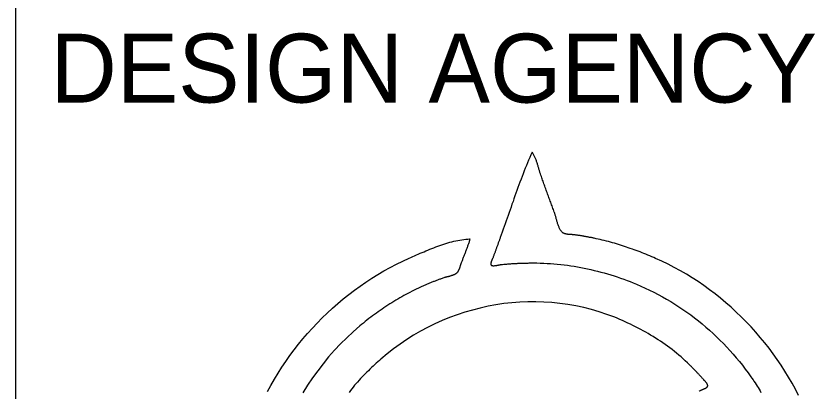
# Model space of a CAD drawing. Extents: x 0 to 34, y 0 to 22.
# Drawn here: x 32 to 33.162, y 4.431 to 4.976 of the extents above; entities that cross this region are included whole.
import ezdxf

# ---------------------------------------------------------------- set-up
doc = ezdxf.new("R2010")
doc.units = 0
for name, color, linetype in [('SH_Border', 7, 'Continuous'), ('SH_Data', 7, 'Continuous'), ('SH_Text', 7, 'Continuous')]:
    doc.layers.add(name, color=color, linetype=linetype)

msp = doc.modelspace()

# ---------------------------------------------------------------- linework, layer by layer
at = {"layer": 'SH_Border'}
msp.add_line((32, 0.5), (32, 21.5), dxfattribs=at)
at = {"layer": 'SH_Text'}
for points in [[(32.7502, 4.7781), (32.7485, 4.7743), (32.7468, 4.7704), (32.7451, 4.7665), (32.7435, 4.7625), (32.742, 4.7585), (32.7404, 4.7546), (32.7388, 4.7506), (32.7372, 4.7466), (32.7357, 4.7426), (32.7342, 4.7386), (32.7326, 4.7346), (32.7312, 4.7306), (32.7297, 4.7265), (32.7283, 4.7225), (32.7268, 4.7185), (32.7254, 4.7144), (32.724, 4.7104), (32.7226, 4.7063), (32.7211, 4.7023), (32.7197, 4.6982), (32.7183, 4.6941), (32.7169, 4.6901), (32.7154, 4.686), (32.7141, 4.682), (32.7126, 4.678), (32.7112, 4.674), (32.7098, 4.6699), (32.7084, 4.6659), (32.7069, 4.6619), (32.7055, 4.6579), (32.704, 4.654)], [(32.7626, 4.7464), (32.7622, 4.7474), (32.7618, 4.7483), (32.7616, 4.7493), (32.7612, 4.7503), (32.761, 4.7514), (32.7606, 4.7524), (32.7603, 4.7535), (32.76, 4.7546), (32.7597, 4.7556), (32.7593, 4.7568), (32.7591, 4.7579), (32.7587, 4.759), (32.7583, 4.7601), (32.758, 4.7612), (32.7576, 4.7623), (32.7572, 4.7634), (32.7569, 4.7644), (32.7565, 4.7655), (32.7561, 4.7666), (32.7557, 4.7677), (32.7553, 4.7687), (32.7548, 4.7698), (32.7545, 4.7708), (32.754, 4.7718), (32.7535, 4.7728), (32.753, 4.7738), (32.7525, 4.7746), (32.7519, 4.7756), (32.7514, 4.7764), (32.7508, 4.7773), (32.7502, 4.7781)], [(32.7826, 4.6909), (32.782, 4.6927), (32.7814, 4.6945), (32.7806, 4.6962), (32.78, 4.698), (32.7793, 4.6998), (32.7787, 4.7016), (32.778, 4.7033), (32.7774, 4.7052), (32.7766, 4.707), (32.776, 4.7087), (32.7753, 4.7105), (32.7747, 4.7123), (32.774, 4.7141), (32.7734, 4.7158), (32.7728, 4.7176), (32.772, 4.7195), (32.7714, 4.7213), (32.7708, 4.723), (32.7701, 4.7248), (32.7695, 4.7266), (32.7689, 4.7284), (32.7682, 4.7301), (32.7675, 4.732), (32.7669, 4.7338), (32.7663, 4.7356), (32.7656, 4.7374), (32.765, 4.7391), (32.7644, 4.7409), (32.7638, 4.7427), (32.7632, 4.7446), (32.7626, 4.7464)], [(32.7948, 4.661), (32.7942, 4.6616), (32.7936, 4.6622), (32.793, 4.6628), (32.7924, 4.6636), (32.7919, 4.6643), (32.7913, 4.6652), (32.7908, 4.6661), (32.7903, 4.667), (32.7899, 4.6679), (32.7895, 4.669), (32.789, 4.67), (32.7886, 4.6711), (32.7883, 4.6722), (32.7878, 4.6733), (32.7874, 4.6744), (32.7871, 4.6756), (32.7868, 4.6767), (32.7865, 4.6779), (32.7861, 4.679), (32.7859, 4.6801), (32.7855, 4.6813), (32.7851, 4.6824), (32.7849, 4.6835), (32.7846, 4.6845), (32.7843, 4.6855), (32.784, 4.6865), (32.7838, 4.6875), (32.7834, 4.6884), (32.7832, 4.6893), (32.7829, 4.6901), (32.7826, 4.6909)], [(32.8108, 4.658), (32.8103, 4.658), (32.8099, 4.6581), (32.8094, 4.6581), (32.8089, 4.6581), (32.8084, 4.6582), (32.8078, 4.6582), (32.8073, 4.6582), (32.8067, 4.6582), (32.8062, 4.6584), (32.8056, 4.6584), (32.805, 4.6584), (32.8045, 4.6584), (32.8039, 4.6585), (32.8033, 4.6585), (32.8028, 4.6586), (32.8022, 4.6586), (32.8016, 4.6587), (32.8011, 4.6587), (32.8005, 4.6588), (32.8, 4.659), (32.7994, 4.6591), (32.7989, 4.6592), (32.7985, 4.6593), (32.7979, 4.6595), (32.7974, 4.6597), (32.7969, 4.6598), (32.7965, 4.6601), (32.796, 4.6603), (32.7956, 4.6605), (32.7952, 4.6608), (32.7948, 4.661)], [(32.5716, 4.6241), (32.5742, 4.6251), (32.5768, 4.6264), (32.5795, 4.6274), (32.5822, 4.6287), (32.5848, 4.6299), (32.5876, 4.6311), (32.5904, 4.6323), (32.5932, 4.6334), (32.596, 4.6346), (32.5988, 4.6358), (32.6017, 4.6369), (32.6045, 4.6381), (32.6074, 4.6392), (32.6103, 4.6403), (32.6132, 4.6414), (32.6161, 4.6424), (32.619, 4.6434), (32.6221, 4.6443), (32.625, 4.6453), (32.6279, 4.6461), (32.6308, 4.647), (32.6338, 4.6478), (32.6367, 4.6485), (32.6396, 4.6491), (32.6425, 4.6498), (32.6455, 4.6502), (32.6484, 4.6507), (32.6513, 4.6512), (32.6542, 4.6515), (32.6571, 4.6517), (32.6599, 4.6519)], [(32.6599, 4.6519), (32.6595, 4.6507), (32.6593, 4.6496), (32.6589, 4.6484), (32.6586, 4.6473), (32.6582, 4.6462), (32.6578, 4.645), (32.6575, 4.6439), (32.6571, 4.6427), (32.6566, 4.6416), (32.6562, 4.6405), (32.6559, 4.6393), (32.6554, 4.6382), (32.655, 4.6371), (32.6546, 4.6361), (32.6542, 4.6348), (32.6537, 4.6338), (32.6533, 4.6327), (32.6529, 4.6316), (32.6525, 4.6304), (32.652, 4.6293), (32.6515, 4.6282), (32.6512, 4.6271), (32.6507, 4.6259), (32.6502, 4.6248), (32.6498, 4.6237), (32.6493, 4.6226), (32.649, 4.6215), (32.6485, 4.6203), (32.6481, 4.6192), (32.6476, 4.6181), (32.6473, 4.617)], [(32.704, 4.654), (32.7037, 4.653), (32.7033, 4.6521), (32.703, 4.6511), (32.7027, 4.6501), (32.7023, 4.6491), (32.702, 4.6482), (32.7016, 4.6472), (32.7012, 4.6462), (32.7009, 4.6453), (32.7006, 4.6443), (32.7003, 4.6433), (32.6999, 4.6425), (32.6995, 4.6415), (32.6992, 4.6405), (32.6988, 4.6396), (32.6984, 4.6386), (32.6981, 4.6376), (32.6977, 4.6367), (32.6975, 4.6357), (32.6971, 4.6347), (32.6967, 4.6338), (32.6964, 4.6328), (32.696, 4.6318), (32.6957, 4.6308), (32.6953, 4.63), (32.6949, 4.629), (32.6946, 4.6281), (32.6942, 4.6271), (32.6938, 4.6261), (32.6935, 4.6251), (32.6932, 4.6242)], [(32.8405, 4.6529), (32.8396, 4.6531), (32.8387, 4.6533), (32.8377, 4.6535), (32.8368, 4.6538), (32.8358, 4.6539), (32.8348, 4.6541), (32.8339, 4.6542), (32.8329, 4.6545), (32.8319, 4.6546), (32.8311, 4.6548), (32.8301, 4.655), (32.8291, 4.6552), (32.8282, 4.6553), (32.8272, 4.6556), (32.8262, 4.6557), (32.8253, 4.6559), (32.8243, 4.6561), (32.8233, 4.6562), (32.8223, 4.6564), (32.8214, 4.6565), (32.8204, 4.6567), (32.8194, 4.6568), (32.8185, 4.657), (32.8175, 4.6571), (32.8165, 4.6573), (32.8156, 4.6574), (32.8147, 4.6575), (32.8137, 4.6576), (32.8128, 4.6578), (32.8118, 4.6579), (32.8108, 4.658)], [(32.9299, 4.6237), (32.9271, 4.6249), (32.9243, 4.6261), (32.9215, 4.6273), (32.9186, 4.6285), (32.9158, 4.6296), (32.913, 4.6307), (32.9102, 4.6319), (32.9073, 4.633), (32.9045, 4.634), (32.9018, 4.6351), (32.8988, 4.6362), (32.8961, 4.6371), (32.8931, 4.6382), (32.8902, 4.6392), (32.8875, 4.6402), (32.8845, 4.6411), (32.8816, 4.642), (32.8787, 4.643), (32.8758, 4.6438), (32.8729, 4.6448), (32.87, 4.6456), (32.8671, 4.6465), (32.8642, 4.6472), (32.8613, 4.6481), (32.8584, 4.6488), (32.8553, 4.6495), (32.8524, 4.6502), (32.8495, 4.651), (32.8465, 4.6517), (32.8436, 4.6523), (32.8405, 4.6529)], [(32.3656, 4.4302), (32.3706, 4.4392), (32.3757, 4.4481), (32.381, 4.4569), (32.3865, 4.4656), (32.3923, 4.4741), (32.3983, 4.4826), (32.4043, 4.4908), (32.4107, 4.4989), (32.4172, 4.5068), (32.424, 4.5147), (32.4309, 4.5223), (32.4379, 4.5298), (32.4452, 4.5371), (32.4526, 4.5443), (32.4601, 4.5513), (32.4678, 4.5581), (32.4757, 4.5648), (32.4837, 4.5712), (32.492, 4.5774), (32.5003, 4.5834), (32.5088, 4.5893), (32.5174, 4.595), (32.5262, 4.6003), (32.535, 4.6055), (32.544, 4.6105), (32.5531, 4.6152), (32.5623, 4.6198), (32.5716, 4.6241)], [(32.6932, 4.6242), (32.6931, 4.6239), (32.693, 4.6237), (32.6929, 4.6234), (32.6927, 4.6232), (32.6926, 4.6228), (32.6925, 4.6226), (32.6924, 4.6222), (32.6921, 4.6219), (32.692, 4.6215), (32.6919, 4.6211), (32.6916, 4.6208), (32.6915, 4.6204), (32.6914, 4.6201), (32.6912, 4.6196), (32.691, 4.6192), (32.6909, 4.6188), (32.6908, 4.6185), (32.6907, 4.618), (32.6906, 4.6176), (32.6904, 4.6173), (32.6904, 4.6169), (32.6903, 4.6165), (32.6903, 4.6162), (32.6902, 4.6158), (32.6902, 4.6154), (32.6902, 4.6152), (32.6903, 4.6148), (32.6903, 4.6146), (32.6904, 4.6144), (32.6906, 4.6141), (32.6907, 4.6139)], [(33.1377, 4.4247), (33.1331, 4.4337), (33.1282, 4.4424), (33.1231, 4.4512), (33.1179, 4.4598), (33.1125, 4.4684), (33.1068, 4.4767), (33.1008, 4.485), (33.0948, 4.4931), (33.0885, 4.501), (33.082, 4.5089), (33.0754, 4.5166), (33.0686, 4.5241), (33.0617, 4.5315), (33.0545, 4.5387), (33.0471, 4.5457), (33.0397, 4.5526), (33.0321, 4.5593), (33.0242, 4.5659), (33.0163, 4.5722), (33.0082, 4.5782), (33.0001, 4.5842), (32.9917, 4.5899), (32.9832, 4.5954), (32.9746, 4.6008), (32.9659, 4.6057), (32.957, 4.6106), (32.9481, 4.6152), (32.939, 4.6196), (32.9299, 4.6237)], [(32.6473, 4.617), (32.647, 4.6165), (32.6469, 4.616), (32.6468, 4.6157), (32.6465, 4.6152), (32.6464, 4.6147), (32.6463, 4.6142), (32.6462, 4.6136), (32.6459, 4.6131), (32.6458, 4.6127), (32.6457, 4.6122), (32.6455, 4.6116), (32.6453, 4.6111), (32.6451, 4.6106), (32.645, 4.61), (32.6447, 4.6095), (32.6446, 4.609), (32.6444, 4.6084), (32.6442, 4.6079), (32.644, 4.6074), (32.6438, 4.607), (32.6435, 4.6065), (32.6433, 4.606), (32.643, 4.6055), (32.6428, 4.605), (32.6425, 4.6047), (32.6423, 4.6042), (32.6421, 4.6038), (32.6417, 4.6034), (32.6415, 4.603), (32.6411, 4.6026), (32.6407, 4.6023)], [(32.6907, 4.6139), (32.6909, 4.6137), (32.6912, 4.6135), (32.6915, 4.6134), (32.6919, 4.6133), (32.6924, 4.6131), (32.6927, 4.6131), (32.6932, 4.613), (32.6937, 4.613), (32.6943, 4.613), (32.6948, 4.613), (32.6954, 4.613), (32.696, 4.6131), (32.6966, 4.6131), (32.6972, 4.6133), (32.6978, 4.6134), (32.6984, 4.6135), (32.699, 4.6135), (32.6997, 4.6136), (32.7003, 4.6137), (32.7009, 4.6139), (32.7015, 4.614), (32.702, 4.6141), (32.7026, 4.6142), (32.7032, 4.6144), (32.7037, 4.6145), (32.7041, 4.6146), (32.7046, 4.6146), (32.705, 4.6147), (32.7055, 4.6148), (32.7057, 4.6148), (32.7061, 4.6148)], [(32.7061, 4.6148), (32.7075, 4.615), (32.7091, 4.6151), (32.7106, 4.6152), (32.712, 4.6153), (32.7136, 4.6154), (32.715, 4.6156), (32.7165, 4.6157), (32.718, 4.6158), (32.7195, 4.6159), (32.721, 4.616), (32.7224, 4.6162), (32.7239, 4.6162), (32.7255, 4.6163), (32.7269, 4.6164), (32.7284, 4.6164), (32.7298, 4.6165), (32.7314, 4.6165), (32.7329, 4.6167), (32.7343, 4.6167), (32.7358, 4.6168), (32.7374, 4.6168), (32.7388, 4.6168), (32.7403, 4.6169), (32.7418, 4.6169), (32.7433, 4.6169), (32.7448, 4.6169), (32.7463, 4.617), (32.7478, 4.617), (32.7492, 4.617), (32.7508, 4.617), (32.7523, 4.617)], [(32.7523, 4.617), (32.7572, 4.617), (32.7622, 4.6169), (32.7672, 4.6167), (32.7722, 4.6164), (32.7771, 4.6162), (32.782, 4.6158), (32.7869, 4.6153), (32.7919, 4.6148), (32.7969, 4.6142), (32.8017, 4.6136), (32.8067, 4.6129), (32.8116, 4.6122), (32.8165, 4.6113), (32.8214, 4.6105), (32.8262, 4.6095), (32.8311, 4.6085), (32.8359, 4.6074), (32.8408, 4.6062), (32.8456, 4.6051), (32.8504, 4.6038), (32.8552, 4.6025), (32.8599, 4.6011), (32.8648, 4.5997), (32.8695, 4.5982), (32.8742, 4.5967), (32.879, 4.5951), (32.8836, 4.5934), (32.8883, 4.5917), (32.8929, 4.5899), (32.8975, 4.588), (32.9021, 4.5862)], [(32.6407, 4.6023), (32.6404, 4.602), (32.6399, 4.6016), (32.6394, 4.6013), (32.639, 4.601), (32.6384, 4.6007), (32.6379, 4.6004), (32.6375, 4.6002), (32.6368, 4.5998), (32.6362, 4.5996), (32.6356, 4.5993), (32.635, 4.5992), (32.6344, 4.599), (32.6338, 4.5987), (32.6332, 4.5986), (32.6326, 4.5983), (32.632, 4.5981), (32.6313, 4.598), (32.6307, 4.5979), (32.6301, 4.5976), (32.6293, 4.5975), (32.6287, 4.5974), (32.6281, 4.5971), (32.6275, 4.597), (32.6269, 4.5969), (32.6263, 4.5968), (32.6257, 4.5965), (32.6251, 4.5964), (32.6245, 4.5963), (32.624, 4.596), (32.6234, 4.5959), (32.6229, 4.5958)], [(32.6229, 4.5958), (32.6218, 4.5954), (32.6206, 4.595), (32.6195, 4.5946), (32.6183, 4.5942), (32.6172, 4.5937), (32.6161, 4.5934), (32.6149, 4.593), (32.6138, 4.5925), (32.6126, 4.5922), (32.6115, 4.5917), (32.6104, 4.5912), (32.6092, 4.5908), (32.6081, 4.5903), (32.607, 4.5899), (32.6058, 4.5895), (32.6047, 4.589), (32.6036, 4.5885), (32.6024, 4.588), (32.6013, 4.5877), (32.6002, 4.5872), (32.5991, 4.5867), (32.5979, 4.5862), (32.5968, 4.5857), (32.5957, 4.5853), (32.5947, 4.5848), (32.5936, 4.5843), (32.5925, 4.5838), (32.5914, 4.5833), (32.5902, 4.5828), (32.5891, 4.5822), (32.588, 4.5817)], [(32.588, 4.5817), (32.585, 4.5804), (32.5819, 4.5788), (32.5789, 4.5774), (32.5759, 4.5759), (32.5728, 4.5743), (32.5698, 4.5728), (32.5668, 4.5712), (32.5639, 4.5696), (32.5608, 4.5679), (32.5579, 4.5662), (32.555, 4.5645), (32.5521, 4.5628), (32.5492, 4.5611), (32.5463, 4.5593), (32.5435, 4.5575), (32.5406, 4.5557), (32.5378, 4.5539), (32.535, 4.5519), (32.5322, 4.5501), (32.5294, 4.5482), (32.5266, 4.5462), (32.5239, 4.5443), (32.5211, 4.5422), (32.5184, 4.5403), (32.5157, 4.5382), (32.5129, 4.5362), (32.5103, 4.5341), (32.5076, 4.532), (32.5051, 4.5298), (32.5024, 4.5277), (32.4997, 4.5256)], [(32.9021, 4.5862), (32.9085, 4.5834), (32.9149, 4.5806), (32.9212, 4.5776), (32.9275, 4.5746), (32.9336, 4.5713), (32.9397, 4.5679), (32.9458, 4.5645), (32.9518, 4.5609), (32.9578, 4.5572), (32.9637, 4.5535), (32.9695, 4.5496), (32.9752, 4.5456), (32.9809, 4.5415), (32.9865, 4.5372), (32.9921, 4.5329), (32.9975, 4.5285), (33.0029, 4.524), (33.0082, 4.5194), (33.0134, 4.5147), (33.0185, 4.5098), (33.0235, 4.505), (33.0285, 4.5), (33.0333, 4.4949), (33.038, 4.4898), (33.0428, 4.4846), (33.0472, 4.4793), (33.0517, 4.474), (33.0561, 4.4685), (33.0603, 4.463), (33.0645, 4.4573), (33.0685, 4.4518)], [(32.8704, 4.5382), (32.8592, 4.5423), (32.848, 4.5461), (32.8368, 4.5494), (32.8254, 4.5523), (32.8139, 4.5547), (32.8023, 4.5568), (32.7907, 4.5583), (32.7792, 4.5594), (32.7675, 4.5603), (32.7558, 4.5605), (32.7441, 4.5605), (32.7325, 4.56), (32.7209, 4.5591), (32.7094, 4.5579), (32.6978, 4.5562), (32.6863, 4.5541), (32.6749, 4.5515), (32.6636, 4.5486), (32.6525, 4.5455), (32.6413, 4.5417), (32.6304, 4.5377), (32.6195, 4.5334), (32.6088, 4.5286), (32.5984, 4.5234), (32.5881, 4.518), (32.5779, 4.512), (32.568, 4.5058), (32.5583, 4.4993), (32.5488, 4.4923), (32.5396, 4.485), (32.5305, 4.4774)], [(32.9791, 4.4691), (32.9761, 4.472), (32.973, 4.4749), (32.97, 4.4777), (32.9669, 4.4805), (32.9636, 4.4832), (32.9604, 4.4858), (32.9572, 4.4885), (32.9539, 4.4911), (32.9505, 4.4936), (32.9472, 4.4961), (32.9438, 4.4986), (32.9403, 4.501), (32.9369, 4.5033), (32.9334, 4.5056), (32.9299, 4.5079), (32.9264, 4.5101), (32.9227, 4.5123), (32.9192, 4.5145), (32.9156, 4.5165), (32.9118, 4.5186), (32.9082, 4.5205), (32.9045, 4.5225), (32.9008, 4.5244), (32.897, 4.5263), (32.8933, 4.5282), (32.8895, 4.5298), (32.8856, 4.5317), (32.8819, 4.5334), (32.878, 4.5349), (32.8742, 4.5366), (32.8704, 4.5382)], [(32.4997, 4.5256), (32.4902, 4.5172), (32.4808, 4.5085), (32.4717, 4.4995), (32.463, 4.4902), (32.4545, 4.4806), (32.4464, 4.4707), (32.4386, 4.4605), (32.4311, 4.45), (32.424, 4.4393), (32.4172, 4.4282)], [(32.5305, 4.4774), (32.5283, 4.4754), (32.526, 4.4734), (32.5237, 4.4713), (32.5214, 4.4692), (32.5191, 4.4672), (32.5168, 4.465), (32.5145, 4.4628), (32.5123, 4.4605), (32.51, 4.4583), (32.5077, 4.456), (32.5054, 4.4537), (32.5032, 4.4514), (32.5011, 4.449), (32.4988, 4.4466), (32.4966, 4.4441), (32.4945, 4.4417), (32.4923, 4.4393), (32.4903, 4.4367), (32.4882, 4.4342), (32.4863, 4.4316), (32.4843, 4.4291)], [(32.9996, 4.4476), (32.999, 4.4484), (32.9984, 4.4491), (32.9977, 4.4498), (32.9971, 4.4504), (32.9964, 4.4512), (32.9957, 4.4519), (32.9951, 4.4526), (32.9945, 4.4533), (32.9938, 4.4541), (32.9932, 4.4547), (32.9926, 4.4554), (32.9918, 4.4561), (32.9912, 4.4569), (32.9905, 4.4576), (32.9899, 4.4582), (32.9893, 4.4589), (32.9886, 4.4597), (32.988, 4.4603), (32.9872, 4.461), (32.9866, 4.4617), (32.9859, 4.4623), (32.9853, 4.463), (32.9846, 4.4638), (32.984, 4.4644), (32.9832, 4.4651), (32.9825, 4.4658), (32.9819, 4.4664), (32.9812, 4.4672), (32.9806, 4.4678), (32.9798, 4.4685), (32.9791, 4.4691)], [(33.0685, 4.4518), (33.0699, 4.4495), (33.0715, 4.4473), (33.0729, 4.4451), (33.0745, 4.4428), (33.076, 4.4405), (33.0774, 4.4383), (33.0789, 4.436), (33.0803, 4.4337), (33.0817, 4.4314), (33.0831, 4.4291)], [(33.0057, 4.4386), (33.0057, 4.4389), (33.0055, 4.4393), (33.0055, 4.4395), (33.0054, 4.4399), (33.0054, 4.4403), (33.0053, 4.4405), (33.0052, 4.4409), (33.0049, 4.4412), (33.0048, 4.4415), (33.0046, 4.4418), (33.0044, 4.4421), (33.0042, 4.4424), (33.004, 4.4428), (33.0037, 4.443), (33.0035, 4.4434), (33.0032, 4.4436), (33.003, 4.444), (33.0027, 4.4443), (33.0025, 4.4445), (33.0023, 4.4449), (33.002, 4.4451), (33.0017, 4.4453), (33.0014, 4.4457), (33.0012, 4.446), (33.0009, 4.4462), (33.0007, 4.4464), (33.0004, 4.4467), (33.0002, 4.4469), (33.0001, 4.4472), (32.9998, 4.4474), (32.9996, 4.4476)], [(32.9997, 4.4339), (32.9998, 4.4341), (33.0001, 4.4342), (33.0003, 4.4342), (33.0006, 4.4343), (33.0007, 4.4344), (33.0009, 4.4346), (33.0012, 4.4347), (33.0014, 4.4347), (33.0018, 4.4348), (33.002, 4.4349), (33.0023, 4.435), (33.0025, 4.4352), (33.0027, 4.4353), (33.003, 4.4354), (33.0032, 4.4355), (33.0035, 4.4356), (33.0037, 4.4359), (33.004, 4.436), (33.0042, 4.4361), (33.0043, 4.4363), (33.0046, 4.4365), (33.0047, 4.4366), (33.0049, 4.4369), (33.0051, 4.437), (33.0052, 4.4372), (33.0053, 4.4375), (33.0054, 4.4377), (33.0055, 4.4378), (33.0055, 4.4381), (33.0057, 4.4383), (33.0057, 4.4386)], [(32.9931, 4.4308), (32.9938, 4.4312), (32.9944, 4.4315), (32.995, 4.4318), (32.9957, 4.4321), (32.9963, 4.4324), (32.9971, 4.4327), (32.9977, 4.433), (32.9984, 4.4333), (32.999, 4.4337), (32.9997, 4.4339)]]:
    msp.add_lwpolyline(points, dxfattribs=at)

# ---------------------------------------------------------------- texts
at = {"layer": 'SH_Data'}
msp.add_text('DESIGN AGENCY', height=0.1, dxfattribs=at).set_placement((32.05, 4.85))

doc.saveas('drawing.dxf')
